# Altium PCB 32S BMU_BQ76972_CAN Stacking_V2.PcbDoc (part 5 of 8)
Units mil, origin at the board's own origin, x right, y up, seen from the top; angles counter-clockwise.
Board outline 7319.29 x 5216.54 mil, 4 copper layers (Top Layer, Layer 1, Layer 2, Bottom Layer), stack 73.068 mil thick; 811 components, 524 nets, 2320 pads, 2669 vias.
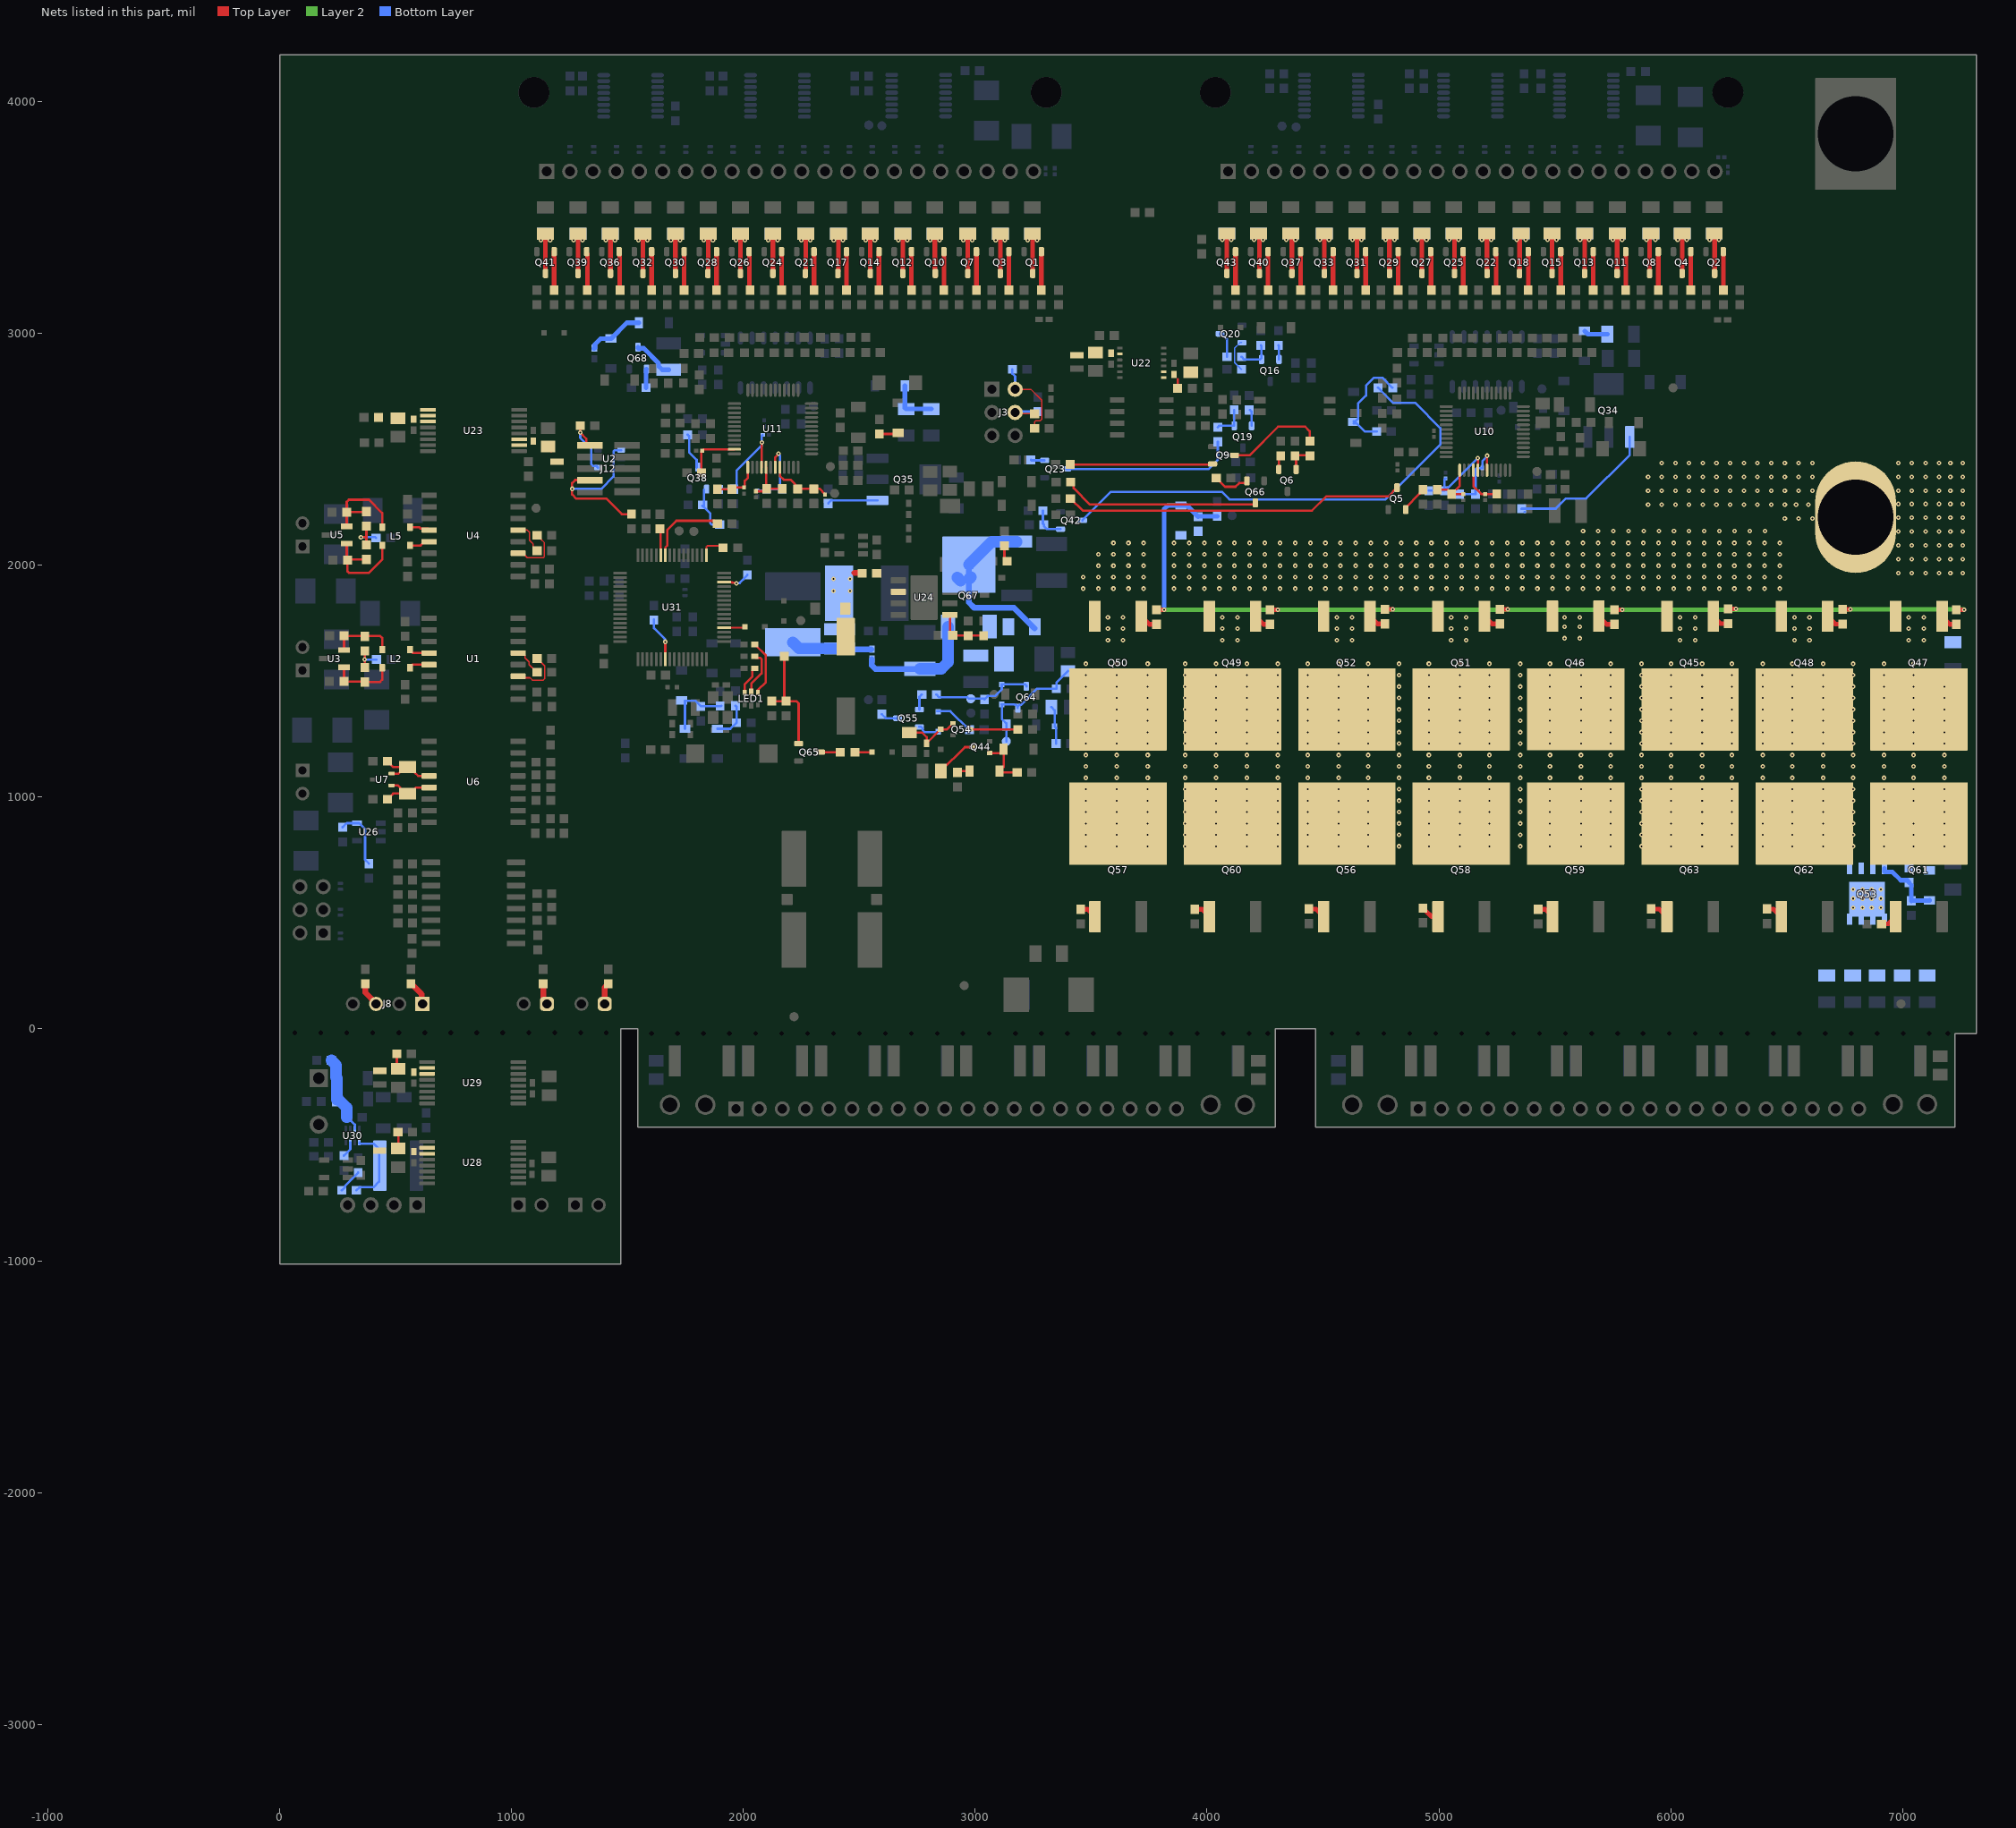
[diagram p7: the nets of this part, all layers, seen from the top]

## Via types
v1: diameter 19.68, hole 7.87, Top Layer to Bottom Layer, tented both sides, 2668 vias
v2: diameter 40, hole 20, Top Layer to Bottom Layer, 1 vias

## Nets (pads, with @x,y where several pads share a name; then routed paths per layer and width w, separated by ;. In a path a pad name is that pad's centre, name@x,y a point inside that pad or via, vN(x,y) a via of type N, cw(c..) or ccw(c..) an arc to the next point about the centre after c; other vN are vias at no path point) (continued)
NetC110_2: C110.2 D13.2 F1.2 Q45.3 Q46.3 Q47.3 Q48.3 Q49.3 Q50.3 Q51.3 Q52.3 R253.2
  other v1: 3572.63,1677.49 3637.96,1677.49 4066.09,1677.49 4131.42,1677.49 4559.55,1677.49 4624.88,1677.49 5053.01,1677.49 5118.34,1677.49 6039.93,1677.49 6105.26,1677.49 6533.39,1677.49 6598.72,1677.49 7026.85,1677.49 7092.18,1677.49 5542.62,1685.46 5607.95,1685.46 3572.63,1726.7 3637.96,1726.7 4066.09,1726.7 4131.42,1726.7 4559.55,1726.7 4624.88,1726.7 5053.01,1726.7 5118.34,1726.7 6039.93,1726.7 6105.26,1726.7 6533.39,1726.7 6598.72,1726.7 7026.85,1726.7 7092.18,1726.7 5542.62,1734.68 5607.95,1734.68 3572.63,1775.92 3637.96,1775.92 4066.09,1775.92 4131.42,1775.92 4559.55,1775.92 4624.88,1775.92 5053.01,1775.92 5118.34,1775.92 5542.62,1775.92 5607.95,1775.92 6039.93,1775.92 6105.26,1775.92 6533.39,1775.92 6598.72,1775.92 7026.85,1775.92 7092.18,1775.92 3465.44,1899.61 3530.76,1899.61 3596.09,1899.61 3661.42,1899.61 3726.74,1899.61 3857.4,1899.61 3922.73,1899.61 3988.05,1899.61 4053.38,1899.61 4118.71,1899.61 4184.03,1899.61 4249.36,1899.61 4314.69,1899.61 4380.02,1899.61 4445.34,1899.61 4510.67,1899.61 4576,1899.61 4641.33,1899.61 4706.65,1899.61 4771.98,1899.61 4837.31,1899.61 4902.63,1899.61 4967.96,1899.61 5033.29,1899.61 5098.62,1899.61 5163.94,1899.61 5229.27,1899.61 5294.6,1899.61 5359.92,1899.61 5425.25,1899.61 5490.58,1899.61 5555.91,1899.61 5621.23,1899.61 5686.56,1899.61 5751.89,1899.61 5817.22,1899.61 5882.54,1899.61 5947.87,1899.61 6013.2,1899.61 6078.52,1899.61 6143.85,1899.61 6209.18,1899.61 6274.51,1899.61 6339.83,1899.61 6405.16,1899.61 6470.49,1899.61 3465.44,1948.82 3530.76,1948.82 3596.09,1948.82 3661.42,1948.82 3726.74,1948.82 3857.4,1948.82 3922.73,1948.82 3988.05,1948.82 4053.38,1948.82 4118.71,1948.82 4184.03,1948.82 4249.36,1948.82 4314.69,1948.82 4380.02,1948.82 4445.34,1948.82 4510.67,1948.82 4576,1948.82 4641.33,1948.82 4706.65,1948.82 4771.98,1948.82 4837.31,1948.82 4902.63,1948.82 4967.96,1948.82 5033.29,1948.82 5098.62,1948.82 5163.94,1948.82 5229.27,1948.82 5294.6,1948.82 5359.92,1948.82 5425.25,1948.82 5490.58,1948.82 5555.91,1948.82 5621.23,1948.82 5686.56,1948.82 5751.89,1948.82 5817.22,1948.82 5882.54,1948.82 5947.87,1948.82 6013.2,1948.82 6078.52,1948.82 6143.85,1948.82 6209.18,1948.82 6274.51,1948.82 6339.83,1948.82 6405.16,1948.82 6470.49,1948.82 6981.09,1966.91 7040.12,1966.91 7099.14,1966.91 7158.17,1966.91 7206.56,1966.91 7260.27,1966.91 3530.76,1998.03 3596.09,1998.03 3661.42,1998.03 3726.74,1998.03 3857.4,1998.03 3922.73,1998.03 3988.05,1998.03 4053.38,1998.03 4118.71,1998.03 4184.03,1998.03 4249.36,1998.03 4314.69,1998.03 4380.02,1998.03 4445.34,1998.03 4510.67,1998.03 4576,1998.03 4641.33,1998.03 4706.65,1998.03 4771.98,1998.03 4837.31,1998.03 4902.63,1998.03 4967.96,1998.03 5033.29,1998.03 5098.62,1998.03 5163.94,1998.03 5229.27,1998.03 5294.6,1998.03 5359.92,1998.03 5425.25,1998.03 5490.58,1998.03 5555.91,1998.03 5621.23,1998.03 5686.56,1998.03 5751.89,1998.03 5817.22,1998.03 5882.54,1998.03 5947.87,1998.03 6013.2,1998.03 6078.52,1998.03 6143.85,1998.03 6209.18,1998.03 6274.51,1998.03 6339.83,1998.03 6405.16,1998.03 6470.49,1998.03 6981.09,2026.76 7040.12,2026.76 7099.14,2026.76 7158.17,2026.76 7206.56,2026.76 7260.27,2026.76 3530.76,2047.24 3596.09,2047.24 3661.42,2047.24 3726.74,2047.24 3857.4,2047.24 3922.73,2047.24 3988.05,2047.24 4053.38,2047.24 4118.71,2047.24 4184.03,2047.24 4249.36,2047.24 4314.69,2047.24 4380.02,2047.24 4445.34,2047.24 4510.67,2047.24 4576,2047.24 4641.33,2047.24 4706.65,2047.24 4771.98,2047.24 4837.31,2047.24 4902.63,2047.24 4967.96,2047.24 5033.29,2047.24 5098.62,2047.24 5163.94,2047.24 5229.27,2047.24 5294.6,2047.24 5359.92,2047.24 5425.25,2047.24 5490.58,2047.24 5555.91,2047.24 5621.23,2047.24 5686.56,2047.24 5751.89,2047.24 5817.22,2047.24 5882.54,2047.24 5947.87,2047.24 6013.2,2047.24 6078.52,2047.24 6143.85,2047.24 6209.18,2047.24 6274.51,2047.24 6339.83,2047.24 6405.16,2047.24 6470.49,2047.24 6981.09,2086.61 7040.12,2086.61 7099.14,2086.61 7158.17,2086.61 7206.56,2086.61 7260.27,2086.61 3596.09,2096.46 3661.42,2096.46 3726.74,2096.46 3857.4,2096.46 3922.73,2096.46 3988.05,2096.46 4053.38,2096.46 4118.71,2096.46 4184.03,2096.46 4249.36,2096.46 4314.69,2096.46 4380.02,2096.46 4445.34,2096.46 4510.67,2096.46 4576,2096.46 4641.33,2096.46 4706.65,2096.46 4771.98,2096.46 4837.31,2096.46 4902.63,2096.46 4967.96,2096.46 5033.29,2096.46 5098.62,2096.46 5163.94,2096.46 5229.27,2096.46 5294.6,2096.46 5359.92,2096.46 5425.25,2096.46 5490.58,2096.46 5555.91,2096.46 5621.23,2096.46 5686.56,2096.46 5751.89,2096.46 5817.22,2096.46 5882.54,2096.46 5947.87,2096.46 6013.2,2096.46 6078.52,2096.46 6143.85,2096.46 6209.18,2096.46 6274.51,2096.46 6339.83,2096.46 6405.16,2096.46 6470.49,2096.46 6981.09,2145.67 7040.12,2145.67 7099.14,2145.67 7158.17,2145.67 7206.56,2145.67 7260.27,2145.67 5622.12,2147.77 5687.45,2147.77 5752.77,2147.77 5818.1,2147.77 5883.43,2147.77 5948.75,2147.77 6014.08,2147.77 6079.41,2147.77 6144.74,2147.77 6210.06,2147.77 6275.39,2147.77 6340.72,2147.77 6406.04,2147.77 6492.55,2202.34 6551.58,2202.34 6610.6,2202.34 6981.09,2205.52 7040.12,2205.52 7099.14,2205.52 7158.17,2205.52 7206.56,2205.52 7260.27,2205.52 5902.28,2262.19 5961.31,2262.19 6020.34,2262.19 6079.36,2262.19 6138.39,2262.19 6197.42,2262.19 6256.44,2262.19 6315.47,2262.19 6374.5,2262.19 6433.52,2262.19 6492.55,2262.19 6540.94,2262.19 6594.64,2262.19 6981.09,2264.57 7040.12,2264.57 7099.14,2264.57 7158.17,2264.57 7206.56,2264.57 7260.27,2264.57 5902.28,2322.04 5961.31,2322.04 6020.34,2322.04 6079.36,2322.04 6138.39,2322.04 6197.42,2322.04 6256.44,2322.04 6315.47,2322.04 6374.5,2322.04 6433.52,2322.04 6492.55,2322.04 6551.58,2322.04 6610.6,2322.04 6981.09,2322.04 7040.12,2322.04 7099.14,2322.04 7158.17,2322.04 7206.56,2322.04 7260.27,2322.04 5902.28,2381.89 5961.31,2381.89 6020.34,2381.89 6079.36,2381.89 6138.39,2381.89 6197.42,2381.89 6256.44,2381.89 6315.47,2381.89 6374.5,2381.89 6433.52,2381.89 6492.55,2381.89 6551.58,2381.89 6610.6,2381.89 6981.09,2381.89 7040.12,2381.89 7099.14,2381.89 7158.17,2381.89 7206.56,2381.89 7260.27,2381.89 5961.31,2440.94 6020.34,2440.94 6079.36,2440.94 6138.39,2440.94 6197.42,2440.94 6256.44,2440.94 6315.47,2440.94 6374.5,2440.94 6433.52,2440.94 6492.55,2440.94 6551.58,2440.94 6610.6,2440.94 6981.09,2440.94 7040.12,2440.94 7099.14,2440.94 7158.17,2440.94 7206.56,2440.94 7260.27,2440.94
NetC112_2: C112.2 R324.1 R328.2 U24.5 | length 226.6
  Top Layer w10: U24.5@2890.83,1785.41 2890.83,1710.2 R328.2@2903.03,1698 2904.41,1696.61 C112.2@2969.89,1696.61 R324.1@3036.59,1696.61
NetC115_1: C115.1 C118.1 L14.2 U23.2 U23.3 | length 52.5
  Top Layer w12: U23.2@1032.89,2517.77 U23.2@1058.28,2517.77 ; U23.3@1045.57,2543.36 U23.3@1046.56,2544.34
  Top Layer w20: C118.1@1153.34,2508.36 C118.1@1157.37,2512.39 C118.1@1171.51,2498.26
NetC117_1: C117.1 C119.1 L15.2 U22.2 | length 24.6
  Top Layer w10: C119.1@3519.03,2917.95 C119.1@3536.46,2935.37
NetC120_1: C120.1 D38.1 Q67.1 R309.2
NetC121_1: C121.1 D39.2 Q67.3 | length 527.2
  Bottom Layer w25: D39.2@2554.43,1595.22 2554.43,1567.77 2569.08,1553.13 C121.1@2761.2,1553.13
  Bottom Layer w50: C121.1@2761.2,1553.13 2853.83,1553.13 2883.12,1582.42 Q67.3@2883.12,1735.24
NetC122_1: C122.1 D39.1 L1.1 | length 351.2
  Bottom Layer w25: L1.1@2414.57,1641.18 2417.65,1638.09 D39.1@2552.27,1638.09
  Bottom Layer w50: C122.1@2213.39,1667.87 2240.08,1641.18 L1.1@2414.57,1641.18
NetC123_1: C123.1 L1.2 R200.1 | length 33
  Top Layer w25: 2479.42,1966.74 2510.5,1966.74 R200.1@2511.84,1965.4
  other v1: 2389.47,1888.94 2460.63,1888.94 2389.47,1941.99 2460.63,1941.99
NetC124_1: C124.1 C126.1 R267.1 U22.7 U22.8 | length 40.4
  Top Layer w10: R267.1@3873.37,2763.42 3873.37,2802.72 3874.15,2803.5
NetC125_1: C125.1 C127.1 R265.1 U23.9 U23.10 U23.11
NetC128_1: C128.1 C129.2 R200.2 U24.2
NetC131_1: C131.1 R317.1 | length 68.5
  Top Layer w10: R317.1@3126.2,2015.51 C131.1@3126.2,2084.03
NetC135_1: C135.1 R266.1 U26.5 | length 271.9
  Bottom Layer w10: C135.1@271.54,869.98 271.54,870.97 285.24,884.67 286.22,884.67 289.25,887.7 343.37,887.7 368.18,862.89 368.18,730.16 384.71,713.63 R266.1@384.71,712.65
NetC137_1: C137.1 Q65.1 R293.2 R294.2 | length 488.8
  Top Layer w10: R294.2@2122.27,1414.24 C137.1@2184.22,1414.24 ; R293.2@2176.72,1606.97 2176.72,1421.73 C137.1@2184.22,1414.24 ; Q65.1@2238.2,1231.25 2238.2,1404.11 2228.07,1414.24 C137.1@2184.22,1414.24
NetC140_2: C140.2 R9.1 R10.2 | length 133.8
  Top Layer w10: R9.1@366.77,1556.16 v1(366.77,1593.56) R10.2@366.77,1636.86
  Bottom Layer w10: v1@364.15,1593.56 v1(366.77,1593.56) C140.2@417.2,1593.56
NetC141_1: C141.1 C143.1 L13.2 R322.1 U28.2 U28.3 | length 74.9
  Top Layer w10: R322.1@510.42,-438.64 R322.1@511.28,-439.5 ; C143.1@511.33,-515.74 R322.1@511.33,-442.1
NetC142_1: C142.1 C144.1 L12.2 R323.1 U29.2 U29.3 | length 67.3
  Top Layer w10: R323.1@505.4,-107.1 505.4,-166.35 C144.1@511.12,-172.07
NetC145_1: C145.1 C146.1 C147.1 R315.2 U30.3 | length 344.1
  Bottom Layer w10: C147.1@281.83,-381.36 289.48,-381.36 C147.1@292.78,-381.36 324.27,-412.86 U30.3@324.27,-430.97
  Bottom Layer w50: R315.2@222.72,-135.3 243.05,-155.63 243.05,-209.12 C146.1@246.39,-212.46 246.95,-213.02 C145.1@246.95,-305.22 ; C145.1@254.6,-305.22 289.48,-340.09 C147.1@289.48,-381.36
NetC148_2: C148.2 R17.1 R20.2 | length 174.6
  Top Layer w10: v1(350.09,2121.19) 372.96,2121.19 374.12,2120.03 ; R17.1@374.12,2088.04 374.12,2120.03 ; R20.2@374.12,2168.96 374.12,2120.03
  Bottom Layer w10: v1@347.47,2121.19 v1(350.09,2121.19) 412.5,2121.19 C148.2@415.39,2118.3
NetC149_1: C149.1 U30.7 | length 68.7
  Bottom Layer w10: C149.1@277.4,-546.72 277.4,-545.73 304.59,-518.55 U30.7@304.59,-489.24
NetC150_2: C150.2 R205.1 R206.1 U10.31 | length 333.2
  Top Layer w10: U10.31@5207.86,2410.2 v1(5207.86,2472.79)
  Bottom Layer w10: R205.1@5089.75,2307.06 R206.1@5158.31,2307.06 5158.31,2413.53 5164.43,2419.65 5186.95,2419.65 C150.2@5187.31,2420.01 5187.31,2449.63 5207.86,2470.17 v1(5207.86,2472.79) v1@5206,2470.94
NetC151_1: C151.1 R318.2 | length 106.7
  Bottom Layer w10: C151.1@267.61,-696.32 268.59,-696.32 282.29,-682.62 282.29,-676.72 338.47,-620.53 R318.2@338.47,-619.55
NetC151_2: C151.2 L11.1 U30.5 | length 353.7
  Bottom Layer w10: C151.2@330.6,-696.32 344.3,-682.62 405.09,-682.62 428.63,-659.08 428.63,-597.9 428.63,-518.17 405.09,-494.63 344.86,-494.63 343.96,-493.72 U30.5@343.96,-489.24
NetC159_2: C159.2 R196.1 R197.1 U10.29 | length 376.9
  Top Layer w10: U10.29@5168.49,2410.2 v1(5168.49,2462.95)
  Bottom Layer w10: R196.1@4956.51,2321.77 R197.1@5024.42,2321.77 R197.1@5024.42,2322.76 ; C159.2@5028.8,2374.02 5024.42,2369.64 R197.1@5024.42,2322.76 ; v1(5168.49,2462.95) 5041.99,2336.46 5038.12,2336.46 R197.1@5024.42,2322.76
NetC160_2: C160.2 R204.1 U10.28 | length 184.7
  Top Layer w10: U10.28@5148.8,2410.2 5148.8,2341.33 5181.14,2308.99 5181.14,2308.01 5181.59,2307.56 R204.1@5250.04,2307.56
NetC161_2: C161.2 R194.1 R195.1 U10.25 | length 237.2
  Top Layer w10: R194.1@4992.76,2326.43 5036.03,2326.43 5054.82,2307.63 5089.75,2342.56 U10.25@5089.75,2410.2 ; R195.1@5054.82,2306.65 5103.99,2306.65 C161.2@5104.84,2307.49
NetC163_2: C163.2 R193.2 U11.23 | length 237.2
  Top Layer w10: R193.2@1819.65,2400.05 1818.73,2400.97 1818.73,2489.92 1829.25,2500.45 U11.23@1961.3,2500.45
NetC164_2: C164.2 R217.1 R222.1 U11.32 | length 267.2
  Top Layer w10: U11.32@2157.16,2422.69 2157.51,2422.34 2157.51,2385.96 2174.13,2369.34 2202.78,2369.34 2242.59,2329.54 R217.1@2303.73,2329.54 2304.68,2330.49 2328.19,2330.49 2352.2,2306.47 C164.2@2352.2,2304.51
NetC165_2: C165.2 R215.1 R223.1 U11.31 | length 333.6
  Top Layer w10: U11.31@2137.48,2422.69 2137.48,2465.8 v1@2152.44,2480.76
  Bottom Layer w10: C165.2@2059.72,2322.3 2093.84,2322.3 R223.1@2100.42,2328.88 R215.1@2167.54,2328.88 2158.12,2338.29 2158.12,2471.86 2151.56,2478.42 v1(2151.56,2481.04)
NetC166_2: C166.2 R212.1 R225.1 U11.29 | length 211.2
  Top Layer w10: C166.2@2054.22,2319.57 2090.03,2319.57 R225.1@2100.69,2330.23 ; U11.29@2098.11,2422.69 2098.11,2332.81 R225.1@2100.69,2330.23 ; R212.1@2167.49,2330.23 R225.1@2100.69,2330.23
NetC167_2: C167.2 R210.1 R226.1 U11.28 | length 460.5
  Top Layer w10: U11.28@2078.42,2422.69 2078.42,2528.65 v1(2079.75,2529.97)
  Bottom Layer w10: R210.1@1891.89,2328.5 R226.1@1958.92,2328.5 1970.48,2340.05 1970.48,2407.88 2078.59,2515.99 2078.59,2528.82 v1(2079.75,2529.97) 2079.75,2558.5 C167.2@2083.73,2562.49
NetC168_2: C168.2 R202.1 R227.1 U11.25 | length 208.2
  Top Layer w10: R202.1@1892.06,2328.5 R227.1@1951.08,2328.5 ; R227.1@1951.08,2328.07 1958.34,2335.32 C168.2@2003.15,2335.32 2005.94,2338.11 2005.94,2363.74 2019.37,2377.17 U11.25@2019.37,2422.69
NetD2_1: D2.1 R201.2 | length 104
  Bottom Layer w20: D2.1@5628.49,3010.89 5642.15,2997.22 R201.2@5726.79,2997.22
NetD3_1: D3.1 R213.2 R214.2 | length 210.9
  Bottom Layer w20: D3.1@2696.81,2774.41 2696.81,2679.43 R213.2@2702.22,2674.02 R214.2@2810.49,2674.02
NetD6_1: D6.1 R198.1 | length 83
  Top Layer w10: R198.1@2586.94,2566.58 2661.07,2566.58 D6.1@2667.32,2572.83
NetD8_1: D8.1 R216.1 R219.2 | length 440.6
  Bottom Layer w10: D8.1@4632.28,2612.2 4644.99,2612.2 4680,2577.19 R216.1@4731.53,2577.19 ; D8.1@4632.28,2622.05 4641.61,2622.05 4651.39,2631.83 4651.39,2697.15 4686.13,2731.89 4686.13,2774.32 4720.87,2809.06 4756.05,2809.06 4799.58,2765.53 R219.2@4800.56,2765.53
NetD13_1: D13.1 R253.1 R259.2 R268.1 R270.1 R279.1 R287.1 R289.1 R291.1 R313.1 R316.1 | length 4409.7
  Top Layer w20: R279.1@3781.9,1808.44 v1(3815.59,1808.44) ; R287.1@4271.89,1808.44 v1(4305.59,1808.44) ; R268.1@4767.15,1810.26 v1(4800.85,1810.26) ; R270.1@5262.84,1810.26 v1(5296.54,1810.26) ; R313.1@5757.22,1808.44 v1(5790.91,1808.44) ; R316.1@6247.93,1811.57 v1(6281.63,1811.57) ; R289.1@6742.13,1809.76 v1(6775.83,1809.76) ; R291.1@7231.5,1808.44 v1(7265.2,1808.44)
  Layer 2 w20: v1(3815.59,1808.44) v1(4305.59,1808.44) 6774.51,1808.44 v1(6775.83,1809.76) 7263.88,1809.76 v1(7265.2,1808.44)
  Bottom Layer w20: v1(3815.59,1808.44) 3815.59,2243.22 3830.19,2257.82 D13.1@3887.8,2257.82 3913.74,2257.82 R253.1@3961.99,2209.57 ; R253.1@3961.99,2211.94 R259.2@4044.23,2211.94
NetD17_2: D17.2 U31.52 | length 80.4
  Top Layer w8: U31.52@1917.19,1730.52 D17.2@1997.56,1730.52
NetD21_1: D21.1 D22.1 Q44.1 R303.1 | length 254.5
  Top Layer w10: Q44.1@3063.02,1190.07 3106.12,1190.07 D21.1@3122.38,1206.33 3122.38,1130.21 D22.1@3104.61,1112.44 3110.52,1106.53 R303.1@3180.94,1106.53 R303.1@3186.85,1112.44
NetD22_2: D22.2 R329.2 | length 54.9
  Top Layer w10: R329.2@2923.23,1106.53 2929.13,1112.44 D22.2@2975.68,1112.44
NetD24_1: D24.1 Q45.4 Q46.4 Q47.4 Q48.4 Q49.4 Q50.4 Q51.4 Q52.4 Q53.1 Q53.2 Q53.3 Q56.4 Q57.4 Q58.4 Q59.4 Q60.4 Q61.4 Q62.4 Q63.4 R256.2
  other v1: 3477.55,788 3611,788 3744.44,788 3905.51,788 4038.95,788 4172.39,788 4305.83,788 4433.79,788 4567.23,788 4695.18,788 4828.62,788 4956.58,788 5090.02,788 5217.97,788 5351.41,788 5479.37,788 5612.81,788 5740.76,788 5874.2,788 6002.16,788 6135.6,788 6263.55,788 6397,788 6524.95,788 6658.39,788 6786.34,788 6919.79,788 7047.74,788 7181.18,788 3477.55,837.22 3611,837.22 3744.44,837.22 3905.51,837.22 4038.95,837.22 4172.39,837.22 4305.83,837.22 4433.79,837.22 4567.23,837.22 4695.18,837.22 4828.62,837.22 4956.58,837.22 5090.02,837.22 5217.97,837.22 5351.41,837.22 5479.37,837.22 5612.81,837.22 5740.76,837.22 5874.2,837.22 6002.16,837.22 6135.6,837.22 6263.55,837.22 6397,837.22 6524.95,837.22 6658.39,837.22 6786.34,837.22 6919.79,837.22 7047.74,837.22 7181.18,837.22 3477.55,886.43 3611,886.43 3744.44,886.43 3905.51,886.43 4038.95,886.43 4172.39,886.43 4305.83,886.43 4433.79,886.43 4567.23,886.43 4695.18,886.43 4828.62,886.43 4956.58,886.43 5090.02,886.43 5217.97,886.43 5351.41,886.43 5479.37,886.43 5612.81,886.43 5740.76,886.43 5874.2,886.43 6002.16,886.43 6135.6,886.43 6263.55,886.43 6397,886.43 6524.95,886.43 6658.39,886.43 6786.34,886.43 6919.79,886.43 7047.74,886.43 7181.18,886.43 3477.55,935.64 3611,935.64 3744.44,935.64 3905.51,935.64 4038.95,935.64 4172.39,935.64 4305.83,935.64 4433.79,935.64 4567.23,935.64 4695.18,935.64 4828.62,935.64 4956.58,935.64 5090.02,935.64 5217.97,935.64 5351.41,935.64 5479.37,935.64 5612.81,935.64 5740.76,935.64 5874.2,935.64 6002.16,935.64 6135.6,935.64 6263.55,935.64 6397,935.64 6524.95,935.64 6658.39,935.64 6786.34,935.64 6919.79,935.64 7181.18,935.64 3477.55,984.85 3611,984.85 3744.44,984.85 3905.51,984.85 4038.95,984.85 4172.39,984.85 4305.83,984.85 4433.79,984.85 4567.23,984.85 4695.18,984.85 4828.62,984.85 4956.58,984.85 5090.02,984.85 5217.97,984.85 5351.41,984.85 5479.37,984.85 5612.81,984.85 5740.76,984.85 5874.2,984.85 6002.16,984.85 6135.6,984.85 6263.55,984.85 6397,984.85 6524.95,984.85 6658.39,984.85 6786.34,984.85 6919.79,984.85 7047.74,984.85 7181.18,984.85 3477.55,1034.07 3611,1034.07 3744.44,1034.07 3905.51,1034.07 4038.95,1034.07 4172.39,1034.07 4305.83,1034.07 4433.79,1034.07 4567.23,1034.07 4695.18,1034.07 4828.62,1034.07 4956.58,1034.07 5090.02,1034.07 5217.97,1034.07 5351.41,1034.07 5479.37,1034.07 5612.81,1034.07 5740.76,1034.07 5874.2,1034.07 6002.16,1034.07 6135.6,1034.07 6263.55,1034.07 6397,1034.07 6524.95,1034.07 6658.39,1034.07 6786.34,1034.07 6919.79,1034.07 7047.74,1034.07 7181.18,1034.07 3477.55,1083.28 3611,1083.28 3744.44,1083.28 3905.51,1083.28 4038.95,1083.28 4172.39,1083.28 4305.83,1083.28 4433.79,1083.28 4567.23,1083.28 4695.18,1083.28 4828.62,1083.28 4956.58,1083.28 5090.02,1083.28 5217.97,1083.28 5351.41,1083.28 5479.37,1083.28 5612.81,1083.28 5740.76,1083.28 5874.2,1083.28 6002.16,1083.28 6135.6,1083.28 6263.55,1083.28 6397,1083.28 6524.95,1083.28 6658.39,1083.28 6786.34,1083.28 6919.79,1083.28 7047.74,1083.28 7181.18,1083.28 3477.55,1132.49 3611,1132.49 3744.44,1132.49 3905.51,1132.49 4038.95,1132.49 4172.39,1132.49 4305.83,1132.49 4433.79,1132.49 4567.23,1132.49 4695.18,1132.49 4828.62,1132.49 4956.58,1132.49 5090.02,1132.49 5217.97,1132.49 5351.41,1132.49 5479.37,1132.49 5612.81,1132.49 5740.76,1132.49 5874.2,1132.49 6002.16,1132.49 6135.6,1132.49 6263.55,1132.49 6397,1132.49 6524.95,1132.49 6658.39,1132.49 6786.34,1132.49 6919.79,1132.49 7047.74,1132.49 7181.18,1132.49 3477.55,1181.7 3611,1181.7 3744.44,1181.7 3905.51,1181.7 4038.95,1181.7 4172.39,1181.7 4305.83,1181.7 4433.79,1181.7 4567.23,1181.7 4695.18,1181.7 4828.62,1181.7 4956.58,1181.7 5090.02,1181.7 5217.97,1181.7 5351.41,1181.7 5479.37,1181.7 5612.81,1181.7 5740.76,1181.7 5874.2,1181.7 6002.16,1181.7 6135.6,1181.7 6263.55,1181.7 6397,1181.7 6524.95,1181.7 6658.39,1181.7 6786.34,1181.7 6919.79,1181.7 7047.74,1181.7 7181.18,1181.7 3477.55,1230.92 3611,1230.92 3744.44,1230.92 3905.51,1230.92 4038.95,1230.92 4172.39,1230.92 4305.83,1230.92 4433.79,1230.92 4567.23,1230.92 4695.18,1230.92 4828.62,1230.92 4956.58,1230.92 5090.02,1230.92 5217.97,1230.92 5351.41,1230.92 5479.37,1230.92 5612.81,1230.92 5740.76,1230.92 5874.2,1230.92 6002.16,1230.92 6135.6,1230.92 6263.55,1230.92 6397,1230.92 6524.95,1230.92 6658.39,1230.92 6786.34,1230.92 6919.79,1230.92 7047.74,1230.92 7181.18,1230.92 3477.55,1280.13 3611,1280.13 3744.44,1280.13 3905.51,1280.13 4038.95,1280.13 4172.39,1280.13 4305.83,1280.13 4433.79,1280.13 4567.23,1280.13 4695.18,1280.13 4828.62,1280.13 4956.58,1280.13 5090.02,1280.13 5217.97,1280.13 5351.41,1280.13 5479.37,1280.13 5612.81,1280.13 5740.76,1280.13 5874.2,1280.13 6002.16,1280.13 6135.6,1280.13 6263.55,1280.13 6397,1280.13 6524.95,1280.13 6658.39,1280.13 6786.34,1280.13 6919.79,1280.13 7047.74,1280.13 7181.18,1280.13 3477.55,1329.34 3611,1329.34 3744.44,1329.34 3905.51,1329.34 4038.95,1329.34 4172.39,1329.34 4305.83,1329.34 4433.79,1329.34 4567.23,1329.34 4695.18,1329.34 4828.62,1329.34 4956.58,1329.34 5090.02,1329.34 5217.97,1329.34 5351.41,1329.34 5479.37,1329.34 5612.81,1329.34 5740.76,1329.34 5874.2,1329.34 6002.16,1329.34 6135.6,1329.34 6263.55,1329.34 6397,1329.34 6524.95,1329.34 6658.39,1329.34 6786.34,1329.34 6919.79,1329.34 7047.74,1329.34 7181.18,1329.34 3477.55,1378.56 3611,1378.56 3744.44,1378.56 3905.51,1378.56 4038.95,1378.56 4172.39,1378.56 4305.83,1378.56 4433.79,1378.56 4567.23,1378.56 4695.18,1378.56 4828.62,1378.56 4956.58,1378.56 5090.02,1378.56 5217.97,1378.56 5351.41,1378.56 5479.37,1378.56 5612.81,1378.56 5740.76,1378.56 5874.2,1378.56 6002.16,1378.56 6135.6,1378.56 6263.55,1378.56 6397,1378.56 6524.95,1378.56 6658.39,1378.56 6786.34,1378.56 6919.79,1378.56 7047.74,1378.56 7181.18,1378.56 3477.55,1427.77 3611,1427.77 3744.44,1427.77 3905.51,1427.77 4038.95,1427.77 4172.39,1427.77 4305.83,1427.77 4433.79,1427.77 4567.23,1427.77 4695.18,1427.77 4828.62,1427.77 4956.58,1427.77 5090.02,1427.77 5217.97,1427.77 5351.41,1427.77 5479.37,1427.77 5612.81,1427.77 5740.76,1427.77 5874.2,1427.77 6002.16,1427.77 6135.6,1427.77 6263.55,1427.77 6397,1427.77 6524.95,1427.77 6658.39,1427.77 6786.34,1427.77 6919.79,1427.77 7047.74,1427.77 7181.18,1427.77 3477.55,1476.98 3611,1476.98 3744.44,1476.98 3905.51,1476.98 4038.95,1476.98 4172.39,1476.98 4305.83,1476.98 4433.79,1476.98 4567.23,1476.98 4695.18,1476.98 4828.62,1476.98 4956.58,1476.98 5090.02,1476.98 5217.97,1476.98 5351.41,1476.98 5479.37,1476.98 5612.81,1476.98 5740.76,1476.98 5874.2,1476.98 6002.16,1476.98 6135.6,1476.98 6263.55,1476.98 6397,1476.98 6524.95,1476.98 6658.39,1476.98 6786.34,1476.98 6919.79,1476.98 7047.74,1476.98 7181.18,1476.98 3477.55,1526.19 3611,1526.19 3744.44,1526.19 3905.51,1526.19 4038.95,1526.19 4172.39,1526.19 4305.83,1526.19 4433.79,1526.19 4567.23,1526.19 4695.18,1526.19 4828.62,1526.19 4956.58,1526.19 5090.02,1526.19 5217.97,1526.19 5351.41,1526.19 5479.37,1526.19 5612.81,1526.19 5740.76,1526.19 5874.2,1526.19 6002.16,1526.19 6135.6,1526.19 6263.55,1526.19 6397,1526.19 6524.95,1526.19 6658.39,1526.19 6786.34,1526.19 6919.79,1526.19 7047.74,1526.19 3477.55,1575.41 3611,1575.41 3744.44,1575.41 3905.51,1575.41 4038.95,1575.41 4172.39,1575.41 4305.83,1575.41 4433.79,1575.41 4567.23,1575.41 4695.18,1575.41 4828.62,1575.41 4956.58,1575.41 5090.02,1575.41 5217.97,1575.41 5351.41,1575.41 5479.37,1575.41 5612.81,1575.41 5740.76,1575.41 5874.2,1575.41 6002.16,1575.41 6135.6,1575.41 6263.55,1575.41 6397,1575.41 6524.95,1575.41 6658.39,1575.41 6786.34,1575.41 6919.79,1575.41 7047.74,1575.41
NetD24_2: D24.2 Q53.4 R256.1 R258.2 | length 286.6
  Bottom Layer w20: Q53.4@6921.85,691.82 6921.85,679.64 6923.85,677.64 6956.08,677.64 6992.15,641.57 7019.23,641.57 7027.93,632.87 R256.1@7027.93,631.89 ; R256.1@7037.77,621.06 R258.2@7037.77,552.64 7038.71,553.57 7115.58,553.57 D24.2@7116.51,554.51
NetD25_2: D25.2 D28.1 Q54.1 R272.2 | length 257.9
  Top Layer w10: R272.2@2716.46,1278.36 2771.23,1278.36 2790.56,1259.03 D28.1@2790.56,1232.08 2850.91,1292.43 D25.2@2851.13,1292.43 2878.2,1292.43 Q54.1@2903.79,1318.02
NetD26_1: D26.1 R273.2 | length 171.8
  Bottom Layer w10: D26.1@2836.64,1370.58 2893.33,1370.58 2973.13,1290.78 R273.2@2975.37,1290.78
NetD26_2: D26.2 Q55.2 | length 95.3
  Bottom Layer w10: Q55.2@2759.36,1302.89 2766.74,1302.89 2773.48,1296.15 2773.48,1288.77 2781.48,1280.77 D26.2@2841.16,1280.77
NetD27_1: D27.1 D29.1 DSG.1 Q64.2 R274.2 R282.2 | length 536.3
  Bottom Layer w10: D27.1@3114.53,1399.8 3169.98,1399.8 3171.93,1397.86 3176.73,1397.86 Q64.2@3183.48,1391.11 ; D27.1@3114.67,1393.05 3114.67,1336.89 3120.52,1331.03 3121.19,1331.03 3134.21,1318.02 D29.1@3134.21,1312.02 DSG.1@3134.21,1240.51 ; Q64.2@3183.48,1383.73 Q64.2@3183.48,1391.11 ; R274.2@3400.18,1543.79 3350.39,1494 R282.2@3350.39,1467.77 3267.51,1467.77 3197.6,1397.86 3190.22,1397.86 Q64.2@3183.48,1391.11
NetD27_2: D27.2 Q64.3 R271.1 R275.2 TP10.1 | length 442.2
  Bottom Layer w10: R271.1@2832.76,1442.73 2844.75,1430.73 2966.66,1430.73 2972.89,1424.5 3037.37,1424.5 R275.2@3040.45,1421.42 3040.45,1422.41 3054.15,1436.11 3086.1,1436.11 3114.53,1464.54 D27.2@3114.53,1486.42 ; D27.2@3114.67,1487.23 3214.14,1487.23 3220.88,1480.49 Q64.3@3220.88,1478.22
NetD30_1: D30.1 R281.2 R283.1 | length 166
  Bottom Layer w10: R283.1@3328.11,1388.43 3342.52,1374.02 D30.1@3342.52,1305.29 3348.71,1299.1 R281.2@3348.71,1230.92
NetD31_1: D31.1 R292.2 | length 74.2
  Top Layer w10: R292.2@2480.94,1193.85 D31.1@2555.12,1193.85
NetD32_1: D32.1 R299.2 R300.1 | length 168.7
  Bottom Layer w10: D32.1@1888.2,1294.78 1943.7,1294.78 1969.5,1320.58 R300.1@1970.48,1320.58 1970.48,1390.13 R299.2@1966.1,1394.51
NetD33_1: D33.1 D35.1 R302.2 R306.1 | length 290.2
  Bottom Layer w10: D33.1@1748.2,1294.78 1748.2,1415.85 1793.08,1415.85 1816.22,1392.7 R306.1@1816.22,1391.72 1902.79,1391.72 R302.2@1905.58,1394.51
NetD40_1: D40.1 D41.1 R224.1 | length 248.5
  Bottom Layer w20: R224.1@1355.32,2934.74 1358.94,2938.36 1358.94,2952.37 1384.66,2978.09 D40.1@1429.35,2978.09 1497.26,3046 D41.1@1549.54,3046
NetJ3_2: J3.2 R43.1 R53.1 | length 370.7
  Top Layer w6: J3.2@3172.23,2759.26 3239.67,2759.26 3286.73,2712.2 3286.73,2630.23 3280.28,2623.79 3261.1,2623.79 3256.04,2618.73 R53.1@3256.04,2591.03
  Bottom Layer w10: R43.1@3160.26,2845.89 3160.26,2827.19 3172.23,2815.22 J3.2@3172.23,2759.26
NetJ3_4: J3.4 R44.1 R46.1 | length 185.9
  Top Layer w6: J3.4@3172.23,2659.26 3177.99,2653.49 R46.1@3256.04,2653.49
  Bottom Layer w10: J3.4@3172.23,2659.26 3175.88,2662.91 R44.1@3270.36,2662.91
NetJ6_1: J6.1 R49.2 | length 93.7
  Top Layer w25: R49.2@1136.57,194.66 1136.57,123.83 J6.1@1152.36,108.05 ; R49.2@1136.57,196.63 R49.2@1136.97,196.24
NetJ7_1: J7.1 R48.2 | length 106.1
  Top Layer w25: J7.1@1411.12,117.28 J7.1@1401.89,108.05 1401.89,179.23 R48.2@1417.32,194.66
NetJ8_1: J8.1 R187.1 | length 109.3
  Top Layer w25: R187.1@565.71,196.63 612.4,149.94 612.4,111.48 J8.1@615.84,108.05
NetJ8_3: J8.3 R1.2 | length 108
  Top Layer w25: R1.2@368.86,196.63 R1.2@368.86,194.66 368.86,157.25 415.84,110.27 J8.3@415.84,108.05
NetJ12_4: J12.4 R4.1 U2.1 | length 765.3
  Top Layer w10: J12.4@1337.2,2367.61 1274.62,2367.61 1261.39,2354.38 v1(1261.39,2329.97) 1261.39,2305.55 1279.9,2287.05 1409.57,2287.05 1475.8,2220.81 R4.1@1517.43,2220.81
  Bottom Layer w10: v1(1261.39,2329.97) 1387.41,2329.97 1440.17,2382.72 1440.17,2490.91 1446.02,2496.77 U2.1@1472.95,2496.77
NetJ12_10: J12.10 R305.1 U2.4 | length 329
  Top Layer w10: R305.1@1296.61,2601.68 1296.44,2601.52 v1(1296.44,2572.06) 1322.64,2545.87 1322.64,2532.18 J12.10@1337.2,2517.61 1312.2,2517.61 J12.10@1302.63,2527.18
  Bottom Layer w10: v1(1296.44,2572.06) 1296.44,2549.55 1343.81,2502.18 1343.81,2437.34 1353.36,2427.79 1366.73,2427.79 U2.4@1372.56,2421.96
NetL2_1: L2.1 U1.12 | length 90.5
  Top Layer w10: L2.1@562.12,1636.86 562.12,1633.91 574.4,1621.63 U1.12@644.56,1621.63
NetL2_2: L2.2 L4.1 R10.1 U3.2 | length 279
  Top Layer w10: U3.2@277.67,1634.9 L4.1@277.67,1695.92 432.71,1695.92 442.04,1686.59 L2.2@442.04,1636.86
NetL2_3: L2.3 L3.1 R9.2 U3.1 | length 283.1
  Top Layer w10: U3.1@277.67,1560.09 277.67,1499.54 L3.1@277.2,1499.07 364.27,1499.07 R9.2@367.07,1496.27 431.88,1496.27 442.04,1506.43 L2.3@442.04,1558.12
NetL2_4: L2.4 U1.13 | length 89.8
  Top Layer w10: L2.4@562.12,1558.12 562.12,1561.08 572.67,1571.63 U1.13@644.56,1571.63
NetL5_1: L5.1 U4.12 | length 87.6
  Top Layer w10: L5.1@562.12,2164.45 601.49,2164.45 607.05,2158.89 637.74,2158.89 U4.12@644.56,2152.08
NetL5_2: L5.2 L7.1 R20.1 U5.2 | length 433.7
  Top Layer w10: U5.2@289.27,2168.07 289.27,2228.83 L7.1@289.01,2229.09 ; R20.1@374.12,2231.96 371.26,2229.09 L7.1@289.01,2229.09 ; L5.2@442.04,2164.45 442.04,2225.74 384.95,2282.83 298.31,2282.83 289.01,2273.52 L7.1@289.01,2229.09
NetL5_3: L5.3 L6.1 R17.2 U5.1 | length 441.5
  Top Layer w10: U5.1@289.27,2093.27 289.27,2025.59 L6.1@289.81,2025.05 ; R17.2@374.12,2025.05 L6.1@289.81,2025.05 ; L5.3@442.04,2085.71 442.04,2024.98 384.95,1967.9 298.31,1967.9 292.46,1973.75 L6.1@292.46,2022.4 L6.1@289.81,2025.05
NetL5_4: L5.4 U4.13 | length 89.2
  Top Layer w10: L5.4@562.12,2085.71 607.52,2085.71 623.89,2102.08 U4.13@644.56,2102.08
NetL8_1: L8.1 R29.2 U6.13 U7.1 | length 275.8
  Top Layer w10: L8.1@464.68,991.17 465.66,991.17 489.87,1015.38 R29.2@540.46,1015.38 ; U7.1@482.39,1050.25 510.19,1050.25 519.87,1040.56 519.87,1035.97 R29.2@540.46,1015.38 ; U6.13@644.56,1041.17 587.91,1041.17 562.12,1015.38 R29.2@551.29,1015.38 R29.2@540.46,1015.38
NetL9_1: L9.1 R29.1 U6.12 U7.2 | length 277.9
  Top Layer w10: L9.1@464.68,1154.58 465.66,1154.58 490.69,1129.55 R29.1@540.46,1129.55 ; U7.2@482.39,1101.43 512.34,1101.43 R29.1@540.46,1129.55 ; U6.12@644.56,1091.17 597.07,1091.17 582.71,1105.54 582.71,1108.96 562.12,1129.55 R29.1@551.29,1129.55 R29.1@540.46,1129.55
NetLED1_4: LED1.4 R23.2 | length 122.5
  Top Layer w10: LED1.4@2005.63,1451.17 2005.63,1486.61 2037.99,1518.97 2037.99,1543.59 R23.2@2049.8,1555.4
NetLED1_5: LED1.5 R24.2 | length 193.6
  Top Layer w10: LED1.5@2034.17,1454.12 2034.17,1489.7 2078.55,1534.07 2078.55,1595.55 2072.69,1601.4 2055.04,1601.4 R24.2@2049.48,1606.97
NetLED1_6: LED1.6 R25.2 | length 240.7
  Top Layer w10: R25.2@2049.8,1658.5 2096.55,1611.75 2096.55,1495.83 2062.72,1462 LED1.6@2062.72,1451.17
NetQ1_1: Q1.1 R89.1 | length 166.3
  Top Layer w20: R89.1@3285.57,3186.81 Q1.1@3285.57,3353.15
NetQ1_3: Q1.3 R55.2 R57.2 | length 171.9
  Top Layer w20: R55.2@3246.72,3429.92 3248.17,3428.47 Q1.3@3248.17,3258.66
  other v1: 3227.03,3402.36 3266.4,3402.36
NetQ2_1: Q2.1 R90.1 | length 166.3
  Top Layer w20: R90.1@6226.94,3186.81 Q2.1@6226.94,3353.15
NetQ2_3: Q2.3 R56.2 R58.2 | length 172.9
  Top Layer w20: R56.2@6187.94,3430.91 6189.54,3429.31 Q2.3@6189.54,3258.66
  other v1: 6168.26,3403.35 6207.63,3403.35
NetQ3_1: Q3.1 R93.1 | length 166.3
  Top Layer w20: R93.1@3145.46,3186.81 Q3.1@3145.46,3353.15
NetQ3_3: Q3.3 R59.2 R61.2 | length 171.3
  Top Layer w20: Q3.3@3108.06,3258.66 R59.2@3108.06,3429.92
  other v1: 3088.37,3402.36 3127.74,3402.36
NetQ4_1: Q4.1 R94.1 | length 166.3
  Top Layer w20: R94.1@6086.67,3186.81 Q4.1@6086.67,3353.15
NetQ4_3: Q4.3 R60.2 R62.2 | length 172.2
  Top Layer w20: Q4.3@6049.27,3258.66 R60.2@6049.27,3430.91
  other v1: 6029.59,3403.35 6068.96,3403.35
NetQ5_2: Q5.2 R221.1 | length 117.2
  Top Layer w10: Q5.2@4856.69,2240.16 4856.69,2248.03 4917.65,2308.99 4917.65,2312.73 R221.1@4931.35,2326.43
NetQ5_3: Q5.3 R231.2 | length 1481.9
  Top Layer w10: R231.2@3410.66,2287.4 R231.2@3419.68,2278.38 ; R231.2@3412.54,2287.4 3464.21,2235.73 4452.82,2235.73 4514.33,2297.24 4781.89,2297.24 Q5.3@4819.29,2334.65
NetQ6_1: Q6.1 R228.1 R230.2 | length 132.4
  Top Layer w10: Q6.1@4384.25,2413.39 4384.25,2472.44 4386.22,2474.41 4451.18,2474.41 R230.2@4455.12,2470.47
NetQ6_2: Q6.2 R220.2 | length 64.3
  Top Layer w10: Q6.2@4309.45,2413.39 4309.45,2466.54 R220.2@4317.32,2474.41
NetQ7_1: Q7.1 R97.1 | length 166.3
  Top Layer w20: R97.1@3005.35,3186.81 Q7.1@3005.35,3353.15
NetQ7_3: Q7.3 R63.2 R65.2 | length 171.3
  Top Layer w20: Q7.3@2967.95,3258.66 R63.2@2967.95,3429.92
  other v1: 2948.26,3402.36 2987.63,3402.36
NetQ8_1: Q8.1 R98.1 | length 166.3
  Top Layer w20: R98.1@5946.41,3186.81 Q8.1@5946.41,3353.15
NetQ8_3: Q8.3 R64.2 R66.2 | length 174.6
  Top Layer w20: Q8.3@5909.01,3258.66 5909.01,3425.21 R64.2@5914.71,3430.91
  other v1: 5895.02,3403.35 5934.39,3403.35
NetQ9_2: Q9.2 R234.2 | length 613.9
  Top Layer w10: R234.2@3409.75,2435.04 4018.11,2435.04 4020.08,2437.01 Q9.2@4022.05,2435.04
NetQ9_3: Q9.3 R230.1 | length 434.4
  Top Layer w10: Q9.3@4118.5,2474.41 4182.84,2474.41 4306.76,2598.33 4423.6,2598.33 4442.9,2579.03 4442.9,2545.68 R230.1@4455.12,2533.46
NetQ10_1: Q10.1 R101.1 | length 166.4
  Top Layer w20: R101.1@2865.03,3186.81 2865.14,3186.92 2865.14,3353.05 Q10.1@2865.24,3353.15
NetQ10_3: Q10.3 R68.2 R70.2 | length 172.1
  Top Layer w20: R68.2@2825.89,3429.92 2825.89,3268.49 2827.84,3266.54 Q10.3@2827.84,3258.66
  other v1: 2806.2,3402.36 2845.57,3402.36
NetQ11_1: Q11.1 R102.1 | length 166.4
  Top Layer w20: R102.1@5805.9,3186.81 5806.02,3186.94 5806.02,3353.02 Q11.1@5806.15,3353.15
NetQ11_3: Q11.3 R67.2 R69.2 | length 173
  Top Layer w20: Q11.3@5768.75,3258.66 5768.75,3429.19 R67.2@5770.47,3430.91
  other v1: 5750.78,3403.35 5790.15,3403.35
NetQ12_1: Q12.1 R105.1 | length 166.3
  Top Layer w20: R105.1@2725.14,3186.81 Q12.1@2725.14,3353.15
NetQ12_3: Q12.3 R71.2 R73.2 | length 171.4
  Top Layer w20: Q12.3@2687.73,3258.66 2687.73,3429.69 R71.2@2687.97,3429.92
  other v1: 2668.28,3402.36 2707.65,3402.36
NetQ13_1: Q13.1 R106.1 | length 166.3
  Top Layer w20: R106.1@5665.89,3186.81 Q13.1@5665.89,3353.15
NetQ13_3: Q13.3 R72.2 R74.2 | length 172.2
  Top Layer w20: Q13.3@5628.49,3258.66 R72.2@5628.49,3430.91
  other v1: 5608.8,3403.35 5648.17,3403.35
NetQ14_1: Q14.1 R109.1 | length 166.3
  Top Layer w20: R109.1@2585.03,3186.81 Q14.1@2585.03,3353.15
NetQ14_3: Q14.3 R75.2 R77.2 | length 171.3
  Top Layer w20: Q14.3@2547.63,3258.66 R75.2@2547.64,3429.92
  other v1: 2527.95,3402.36 2567.32,3402.36
NetQ15_1: Q15.1 R110.1 | length 166.3
  Top Layer w20: R110.1@5525.62,3186.81 Q15.1@5525.62,3353.15
NetQ15_3: Q15.3 R76.2 R78.2 | length 172.2
  Top Layer w20: Q15.3@5488.22,3258.66 R76.2@5488.22,3430.91
  other v1: 5468.54,3403.35 5507.91,3403.35
NetQ16_1: Q16.1 R240.1 R242.2 | length 150.1
  Bottom Layer w10: R242.2@4148.79,2899.61 4160.6,2887.8 4228.66,2887.8 4235.4,2894.54 4235.4,2945.75 R240.1@4232.16,2948.99
NetQ16_2: Q16.2 R236.2 | length 62.2
  Bottom Layer w10: R236.2@4307.77,2948.99 4310.2,2946.56 Q16.2@4310.2,2887.8
NetQ17_1: Q17.1 R113.1 | length 166.3
  Top Layer w20: R113.1@2444.92,3186.81 Q17.1@2444.92,3353.15
NetQ17_3: Q17.3 R79.2 R81.2 | length 172.1
  Top Layer w20: Q17.3@2407.52,3258.66 2407.52,3266.54 2409.49,3268.5 R79.2@2409.49,3429.92
  other v1: 2389.8,3402.36 2429.17,3402.36
NetQ18_1: Q18.1 R114.1 | length 166.3
  Top Layer w20: R114.1@5385.36,3186.81 Q18.1@5385.36,3353.15
NetQ18_3: Q18.3 R80.2 R82.2 | length 175.3
  Top Layer w20: Q18.3@5347.96,3258.66 5347.96,3423.6 R80.2@5355.26,3430.91
  other v1: 5335.58,3403.35 5374.95,3403.35
NetQ19_1: Q19.1 R241.1 R243.2 | length 142.2
  Bottom Layer w10: R243.2@4046.43,2595.61 4052.33,2601.51 Q19.1@4117.29,2601.51 R241.1@4117.29,2670.41
NetQ19_2: Q19.2 R237.2 | length 71.7
  Bottom Layer w10: R237.2@4185.44,2670.41 4192.09,2663.76 Q19.2@4192.09,2601.51
NetQ20_2: Q20.2 R246.2 | length 146.6
  Bottom Layer w6: R246.2@4148.79,2845.39 4147.8,2845.39 4119.1,2874.09 4119.1,2875.35 4118.1,2876.35 4118.1,2936.04 4142.7,2960.63 Q20.2@4150.57,2960.63
NetQ20_3: Q20.3 R242.1 | length 115.3
  Bottom Layer w10: Q20.3@4056.08,2998.03 4063.96,2998.03 4085.8,2976.19 R242.1@4085.8,2899.61
NetQ21_1: Q21.1 R117.1 | length 166.3
  Top Layer w20: R117.1@2304.81,3186.81 Q21.1@2304.81,3353.15
NetQ21_3: Q21.3 R83.2 R85.2 | length 172.1
  Top Layer w20: Q21.3@2267.41,3258.66 2267.41,3266.54 2269.38,3268.5 R83.2@2269.38,3429.92
  other v1: 2249.69,3402.36 2289.06,3402.36
NetQ22_1: Q22.1 R118.1 | length 167.2
  Top Layer w20: Q22.1@5245.1,3353.15 5245.1,3345.28 5247.07,3343.31 R118.1@5247.07,3186.81
NetQ22_3: Q22.3 R84.2 R86.2 | length 173.1
  Top Layer w20: R84.2@5205.73,3430.91 5207.7,3428.94 Q22.3@5207.7,3258.66
  other v1: 5186.04,3403.35 5225.41,3403.35
NetQ23_2: Q23.2 R247.2 | length 59.9
  Bottom Layer w10: R247.2@3240.16,2454.72 3242.13,2452.76 Q23.2@3299.21,2452.76
NetQ23_3: Q23.3 R243.1 | length 746.9
  Bottom Layer w10: Q23.3@3393.7,2415.35 4007.06,2415.35 4046.43,2454.72 R243.1@4046.43,2532.61
NetQ24_1: Q24.1 R155.1 | length 166.3
  Top Layer w20: R155.1@2164.7,3186.81 Q24.1@2164.7,3353.15
NetQ24_3: Q24.3 R120.2 R122.2 | length 171.3
  Top Layer w20: Q24.3@2127.3,3258.66 R120.2@2127.3,3429.92
  other v1: 2107.62,3402.36 2146.99,3402.36
NetQ25_1: Q25.1 R156.1 | length 166.3
  Top Layer w20: R156.1@5104.84,3186.81 Q25.1@5104.84,3353.15
NetQ25_3: Q25.3 R121.2 R123.2 | length 173.4
  Top Layer w20: R121.2@5064.55,3430.91 5067.44,3428.02 Q25.3@5067.44,3258.66
  other v1: 5044.86,3403.35 5084.23,3403.35
NetQ26_1: Q26.1 R159.1 | length 168
  Top Layer w20: Q26.1@2024.6,3353.15 2026.41,3351.34 2026.41,3188.92 R159.1@2028.52,3186.81
NetQ26_3: Q26.3 R124.2 R126.2 | length 171.5
  Top Layer w20: Q26.3@1987.19,3258.66 1987.19,3429.31 R124.2@1987.8,3429.92
  other v1: 1968.11,3402.36 2007.48,3402.36
NetQ27_1: Q27.1 R160.1 | length 167.6
  Top Layer w20: Q27.1@4964.57,3353.15 4966.05,3351.68 4966.05,3188.28 R160.1@4967.52,3186.81
NetQ27_3: Q27.3 R125.2 R127.2 | length 172.2
  Top Layer w20: Q27.3@4927.17,3258.66 R125.2@4927.17,3430.91
  other v1: 4907.49,3403.35 4946.86,3403.35
NetQ28_1: Q28.1 R163.1 | length 166.3
  Top Layer w20: R163.1@1884.49,3186.81 Q28.1@1884.49,3353.15
NetQ28_3: Q28.3 R128.2 R130.2 | length 172.1
  Top Layer w20: Q28.3@1847.09,3258.66 1847.09,3266.54 1849.05,3268.5 R128.2@1849.05,3429.92
  other v1: 1829.37,3402.36 1868.74,3402.36
NetQ29_1: Q29.1 R164.1 | length 166.3
  Top Layer w20: R164.1@4824.31,3186.81 Q29.1@4824.31,3353.15
NetQ29_3: Q29.3 R129.2 R131.2 | length 173.3
  Top Layer w20: Q29.3@4786.91,3258.66 4786.91,3428.25 R129.2@4789.56,3430.91
  other v1: 4769.88,3403.35 4809.25,3403.35
NetQ30_1: Q30.1 R167.1 | length 166.3
  Top Layer w20: R167.1@1744.38,3186.81 Q30.1@1744.38,3353.15
NetQ30_3: Q30.3 R132.2 R134.2 | length 171.3
  Top Layer w20: Q30.3@1706.98,3258.66 R132.2@1706.98,3429.92
  other v1: 1687.29,3402.36 1726.66,3402.36
NetQ31_1: Q31.1 R168.1 | length 166.3
  Top Layer w20: R168.1@4684.05,3186.81 Q31.1@4684.05,3353.15
NetQ31_3: Q31.3 R133.2 R135.2 | length 172.2
  Top Layer w20: Q31.3@4646.65,3258.66 R133.2@4646.65,3430.91
  other v1: 4626.96,3403.35 4666.33,3403.35
NetQ32_1: Q32.1 R171.1 | length 166.4
  Top Layer w20: Q32.1@1604.27,3353.15 1604.32,3353.1 1604.32,3186.86 R171.1@1604.37,3186.81
NetQ32_3: Q32.3 R136.2 R138.2 | length 171.3
  Top Layer w20: Q32.3@1566.87,3258.66 R136.2@1566.87,3429.92
  other v1: 1547.18,3402.36 1586.55,3402.36
NetQ33_1: Q33.1 R172.1 | length 166.3
  Top Layer w20: R172.1@4543.79,3186.81 Q33.1@4543.79,3353.15
NetQ33_3: Q33.3 R137.2 R139.2 | length 172.2
  Top Layer w20: Q33.3@4506.39,3258.66 R137.2@4506.39,3430.91
  other v1: 4486.7,3403.35 4526.07,3403.35
NetQ34_1: Q34.1 R211.2 | length 642.3
  Bottom Layer w10: R211.2@5356.82,2243.09 R211.2@5356.82,2244.07 5504.16,2244.07 5547.97,2287.88 5635.62,2287.88 5823.34,2475.6 Q34.1@5823.34,2553.53 ; R211.2@5370.52,2229.39 R211.2@5371.5,2229.39
NetQ35_1: Q35.1 R218.2 | length 218
  Bottom Layer w10: R218.2@2365.93,2266.55 R218.2@2365.93,2266.55 2379.63,2280.31 Q35.1@2578.21,2280.31
NetQ36_1: Q36.1 R175.1 | length 167.9
  Top Layer w20: Q36.1@1464.16,3353.15 1465.97,3351.34 1465.97,3188.79 R175.1@1467.95,3186.81
NetQ36_3: Q36.3 R140.2 R142.2 | length 171.4
  Top Layer w20: R140.2@1426.48,3429.92 1426.76,3429.64 Q36.3@1426.76,3258.66
  other v1: 1406.79,3402.36 1446.16,3402.36
NetQ37_1: Q37.1 R176.1 | length 166.3
  Top Layer w20: R176.1@4403.52,3186.81 Q37.1@4403.52,3353.15
NetQ37_3: Q37.3 R141.2 R143.2 | length 174.1
  Top Layer w20: R141.2@4361.64,3430.91 4366.12,3426.42 Q37.3@4366.12,3258.66
  other v1: 4341.96,3403.35 4381.33,3403.35
NetQ38_1: Q38.1 R254.2 R297.2 | length 205.5
  Bottom Layer w10: R297.2@1823.55,2257.19 R297.2@1826.79,2253.95 ; 1829.46,2326.28 1829.46,2256.62 R297.2@1826.79,2253.95 ; R254.2@1897.34,2175.36 1863.73,2175.36 1857.87,2181.21 1857.87,2222.87 R297.2@1826.79,2253.95
NetQ38_3: Q38.3 R235.1 | length 157.1
  Bottom Layer w10: R235.1@1759.84,2562.99 1765.8,2557.04 1765.8,2487.95 1798.32,2455.44 Q38.3@1798.32,2421.87
NetQ39_1: Q39.1 R179.1 | length 167.5
  Top Layer w20: Q39.1@1324.05,3353.15 1324.05,3345.28 1326.84,3342.49 R179.1@1326.84,3186.81
NetQ39_3: Q39.3 R144.2 R146.2 | length 171.3
  Top Layer w20: Q39.3@1286.65,3258.66 R144.2@1286.65,3429.92
  other v1: 1266.97,3402.36 1306.34,3402.36
NetQ40_1: Q40.1 R180.1 | length 166.3
  Top Layer w20: R180.1@4263.26,3186.81 Q40.1@4263.26,3353.15
NetQ40_3: Q40.3 R145.2 R147.2 | length 173.8
  Top Layer w20: R145.2@4222.01,3430.91 4225.86,3427.05 Q40.3@4225.86,3258.66
  other v1: 4202.32,3403.35 4241.69,3403.35
NetQ41_1: Q41.1 R183.1 | length 166.3
  Top Layer w20: R183.1@1183.95,3186.81 Q41.1@1183.95,3353.15
NetQ41_3: Q41.3 R149.2 R151.2 | length 171.3
  Top Layer w20: Q41.3@1146.54,3258.66 R149.2@1146.54,3429.92
  other v1: 1126.86,3402.36 1166.23,3402.36
NetQ42_1: Q42.1 R249.2 R250.2 | length 140
  Bottom Layer w10: R250.2@3291.82,2235.43 3291.82,2179.02 R249.2@3296.07,2174.77 ; R249.2@3296.07,2169.29 3309.41,2155.95 Q42.1@3368.11,2155.95
NetQ42_3: Q42.3 R219.1 | length 2118.9
  Bottom Layer w10: Q42.3@3462.6,2193.35 3586.19,2316.94 4063.96,2316.94 4096.58,2284.32 4769.42,2284.32 4775.37,2290.28 4775.55,2290.28 5006.3,2521.02 5006.3,2592.52 4898.95,2699.87 4820.76,2699.87 4820.63,2699.99 4803.1,2699.99 4752.25,2750.84 4752.25,2751.82 4738.55,2765.53 R219.1@4737.57,2765.53
NetQ43_1: Q43.1 R184.1 | length 166.3
  Top Layer w20: R184.1@4123,3186.81 Q43.1@4123,3353.15
NetQ43_3: Q43.3 R148.2 R150.2 | length 172.4
  Top Layer w20: R148.2@4085.18,3430.91 4085.6,3430.49 Q43.3@4085.6,3258.66
  other v1: 4065.5,3403.35 4104.87,3403.35
NetQ44_3: Q44.3 R255.2 | length 178.6
  Top Layer w10: R255.2@2852.37,1112.44 2955.59,1215.66 Q44.3@2988.22,1215.66
NetQ45_1: Q45.1 R316.2 | length 77.4
  Top Layer w20: Q45.1@6183.53,1780.08 6215.03,1748.58 R316.2@6247.93,1748.58
NetQ46_1: Q46.1 R313.2 | length 81.6
  Top Layer w20: Q46.1@5690.07,1780.28 5724.89,1745.45 R313.2@5757.22,1745.45
NetQ47_1: Q47.1 R291.2 | length 75.4
  Top Layer w20: Q47.1@7170.45,1780.08 7205.07,1745.45 R291.2@7231.5,1745.45
NetQ48_1: Q48.1 R289.2 | length 78.9
  Top Layer w20: Q48.1@6676.99,1780.08 6710.3,1746.77 R289.2@6742.13,1746.77
NetQ49_1: Q49.1 R287.2 | length 76.5
  Top Layer w20: Q49.1@4209.69,1780.08 4244.32,1745.45 R287.2@4271.89,1745.45
NetQ50_1: Q50.1 R279.2 | length 80
  Top Layer w20: Q50.1@3716.24,1780.08 3750.86,1745.45 R279.2@3781.9,1745.45
NetQ51_1: Q51.1 R270.2 | length 79.8
  Top Layer w20: Q51.1@5196.61,1780.08 5229.43,1747.26 R270.2@5262.84,1747.26
NetQ52_1: Q52.1 R268.2 | length 77.6
  Top Layer w20: Q52.1@4703.15,1780.08 4735.97,1747.26 R268.2@4767.15,1747.26
NetQ53_5: Q53.5 Q53.6 Q53.7 Q53.8 Q53.9 R277.1 R278.1 R284.1 R285.1 R286.1
  other v1: 6786.85,522.32 6826.85,522.32 6866.85,522.32 6906.85,522.32 6786.85,562.32 6826.85,562.32 6866.85,562.32 6906.85,562.32 6786.85,602.32 6826.85,602.32 6866.85,602.32 6906.85,602.32
NetQ54_3: Q54.3 R261.2 | length 205.5
  Top Layer w10: Q54.3@2978.59,1292.43 R261.2@3184.09,1292.43
NetQ55_1: Q55.1 R271.2 | length 69.3
  Bottom Layer w10: Q55.1@2759.36,1377.7 2759.36,1432.32 R271.2@2769.77,1442.73
NetQ55_3: Q55.3 R262.2 | length 74.7
  Bottom Layer w10: R262.2@2597.25,1357.46 2614.42,1340.29 Q55.3@2664.87,1340.29
NetQ56_1: Q56.1 R321.1 | length 78
  Top Layer w20: R321.1@4438.98,517.64 4469.85,517.64 Q56.1@4503.15,484.33
NetQ57_1: Q57.1 R314.1 | length 74.4
  Top Layer w20: R314.1@3454.88,515.83 3484.74,515.83 Q57.1@3516.24,484.33
NetQ58_1: Q58.1 R312.1 | length 80.6
  Top Layer w20: R312.1@4931.1,520.83 4956.41,495.52 4957.26,495.52 4968.45,484.33 Q58.1@4996.61,484.33
NetQ59_1: Q59.1 R290.1 | length 74.5
  Top Layer w20: R290.1@5428.59,515.83 5458.58,515.83 Q59.1@5490.07,484.33
NetQ60_1: Q60.1 R288.1 | length 75.9
  Top Layer w20: R288.1@3946.85,515.83 3978.2,515.83 Q60.1@4009.69,484.33
NetQ61_1: Q61.1 R280.1 | length 73.9
  Top Layer w20: R280.1@6909.59,452.83 6938.95,452.83 Q61.1@6970.45,484.33
NetQ62_1: Q62.1 R276.1 | length 75.4
  Top Layer w20: R276.1@6415.4,517.64 6443.68,517.64 Q62.1@6476.99,484.33
NetQ63_1: Q63.1 R269.1 | length 82
  Top Layer w20: R269.1@5915.35,517.64 5950.22,517.64 Q63.1@5983.53,484.33
NetQ65_3: Q65.3 R292.1 | length 85.3
  Top Layer w10: Q65.3@2332.69,1193.85 R292.1@2417.95,1193.85
NetQ66_2: Q66.2 R26.1 | length 160.4
  Top Layer w10: R26.1@4039.76,2375.98 4040.75,2375.98 4077.81,2338.93 4122.47,2338.93 4138.36,2354.82 4164.91,2354.82 4169.69,2359.59 Q66.2@4169.69,2366.14
NetQ66_3: Q66.3 R33.2 | length 853.4
  Top Layer w10: R33.2@3404.34,2353.14 3417.38,2353.14 3424.63,2345.89 3424.63,2332.85 3495.17,2262.3 4202.31,2262.3 4209.06,2269.04 Q66.3@4209.06,2269.69
NetQ67_4: Q67.4 R308.2 R309.1 | length 771.6
  Bottom Layer w25: Q67.4@2972.88,2002.96 2972.88,1940.7 2972.88,1839.82 2996.47,1816.23 3167.5,1816.23 R309.1@3255.4,1728.34
  Bottom Layer w50: Q67.4@2922.35,1947.84 Q67.4@2936.47,1933.72 ; Q67.4@2972.88,1940.7 Q67.4@2981.8,1949.62 ; Q67.4@2972.88,2002.96 3071.85,2101.92 R308.2@3179.09,2101.92
NetQ68_1: Q68.1 R190.2 | length 80.8
  Bottom Layer w20: R190.2@1580.59,2766.49 1580.59,2844.53 Q68.1@1582.52,2846.46
NetQ68_3: Q68.3 R203.1 | length 182.5
  Bottom Layer w20: Q68.3@1545.12,2940.94 1545.12,2937.85 1546.93,2936.04 1570.68,2936.04 1634.85,2871.86 1634.85,2859.13 1650.44,2843.54 R203.1@1678,2843.54
NetR6_2: R6.2 U1.3 | length 225.8
  Top Layer w6: U1.3@1028.31,1524.58 1038.07,1514.82 1080.2,1514.82 1080.2,1514.64 1089.94,1504.9 1136.57,1504.9 1142.78,1511.1 1142.78,1515.06 1142.65,1515.18 1142.65,1565.92 1142.78,1566.05 1111.33,1597.49 R6.2@1110.35,1597.49
NetR7_2: R7.2 U1.5 | length 131.9
  Top Layer w6: U1.5@1028.41,1621.63 1048.91,1621.63 1057.72,1612.82 1057.72,1600.82 1064.1,1594.44 1064.27,1594.44 1075.78,1582.93 1075.78,1572.02 1107.05,1540.75 R7.2@1107.05,1534.43
NetR11_2: R11.2 U31.10 | length 350.8
  Top Layer w10: U31.10@1663.25,2043.51 1664.03,2044.29 1664.03,2077.28 1671.99,2085.24 1671.99,2153.16 1711.11,2192.28 1875.53,2192.28 R11.2@1888.1,2179.71
NetR12_2: R12.2 U31.1 | length 112.5
  Top Layer w8: U31.1@1840.41,2043.51 1840.41,2078.59 1845.1,2083.27 1905.07,2083.27 R12.2@1912.58,2075.76
  Top Layer w10: R12.2@1914.41,2075.9 R12.2@1914.54,2075.76
NetR14_2: R14.2 U4.3 | length 228.5
  Top Layer w6: U4.3@1028.41,2052.08 1049.08,2052.08 1068.22,2032.95 1085.98,2032.95 1086.1,2032.82 1137.17,2032.82 1141.84,2037.49 1141.84,2097.49 1127.03,2112.3 1127.03,2113.29 1111.33,2128.99 R14.2@1110.35,2128.99
NetR15_2: R15.2 U31.11 | length 115.4
  Top Layer w10: R15.2@1640.28,2157.51 1643.56,2154.23 U31.11@1643.56,2043.51
NetR16_2: R16.2 U4.5 | length 147.5
  Top Layer w6: U4.5@1028.41,2152.08 1068.22,2152.08 1077.39,2142.9 1077.39,2108 1086.57,2098.82 1086.75,2098.82 1093.66,2091.91 1093.66,2078.22 1109.36,2062.52 R16.2@1110.35,2062.52
NetR18_2: R18.2 U31.62 | length 118.2
  Top Layer w10: U31.62@1917.19,1927.37 1950.18,1927.37 1953.18,1924.36 1967.62,1924.36 v1(1969.48,1922.51)
  Bottom Layer w10: v1(1969.48,1922.51) 1970.43,1923.47 1983.65,1923.47 1998.88,1938.69 1998.88,1939.07 2017.58,1957.77 R18.2@2017.58,1958.76
NetR19_2: R19.2 U31.39 | length 191.4
  Top Layer w10: U31.39@1663.25,1594.69 v1(1663.25,1669.95)
  Bottom Layer w10: R19.2@1614.17,1765.75 R19.2@1614.17,1763.78 1614.17,1729.09 1661.4,1681.87 1661.4,1671.8 v1(1663.25,1669.95)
